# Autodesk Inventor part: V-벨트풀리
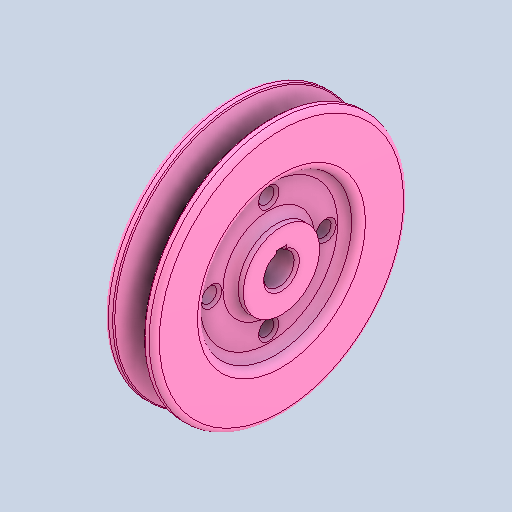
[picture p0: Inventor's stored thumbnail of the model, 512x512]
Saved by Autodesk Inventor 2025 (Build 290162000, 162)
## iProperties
Created: 2025-08
Part Number: V-벨트풀리
Material: 강철, 연강
Document SubType Name: Modeling
Designer: infra02
Density: 7.86 g/cm^3
Appearance: 기본값
Author: jhkim
Sending System: Autodesk Inventor 2026
Preprocessor: ST-DEVELOPER v20.1
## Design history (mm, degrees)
feature "솔리드1"
node "솔리드2"
